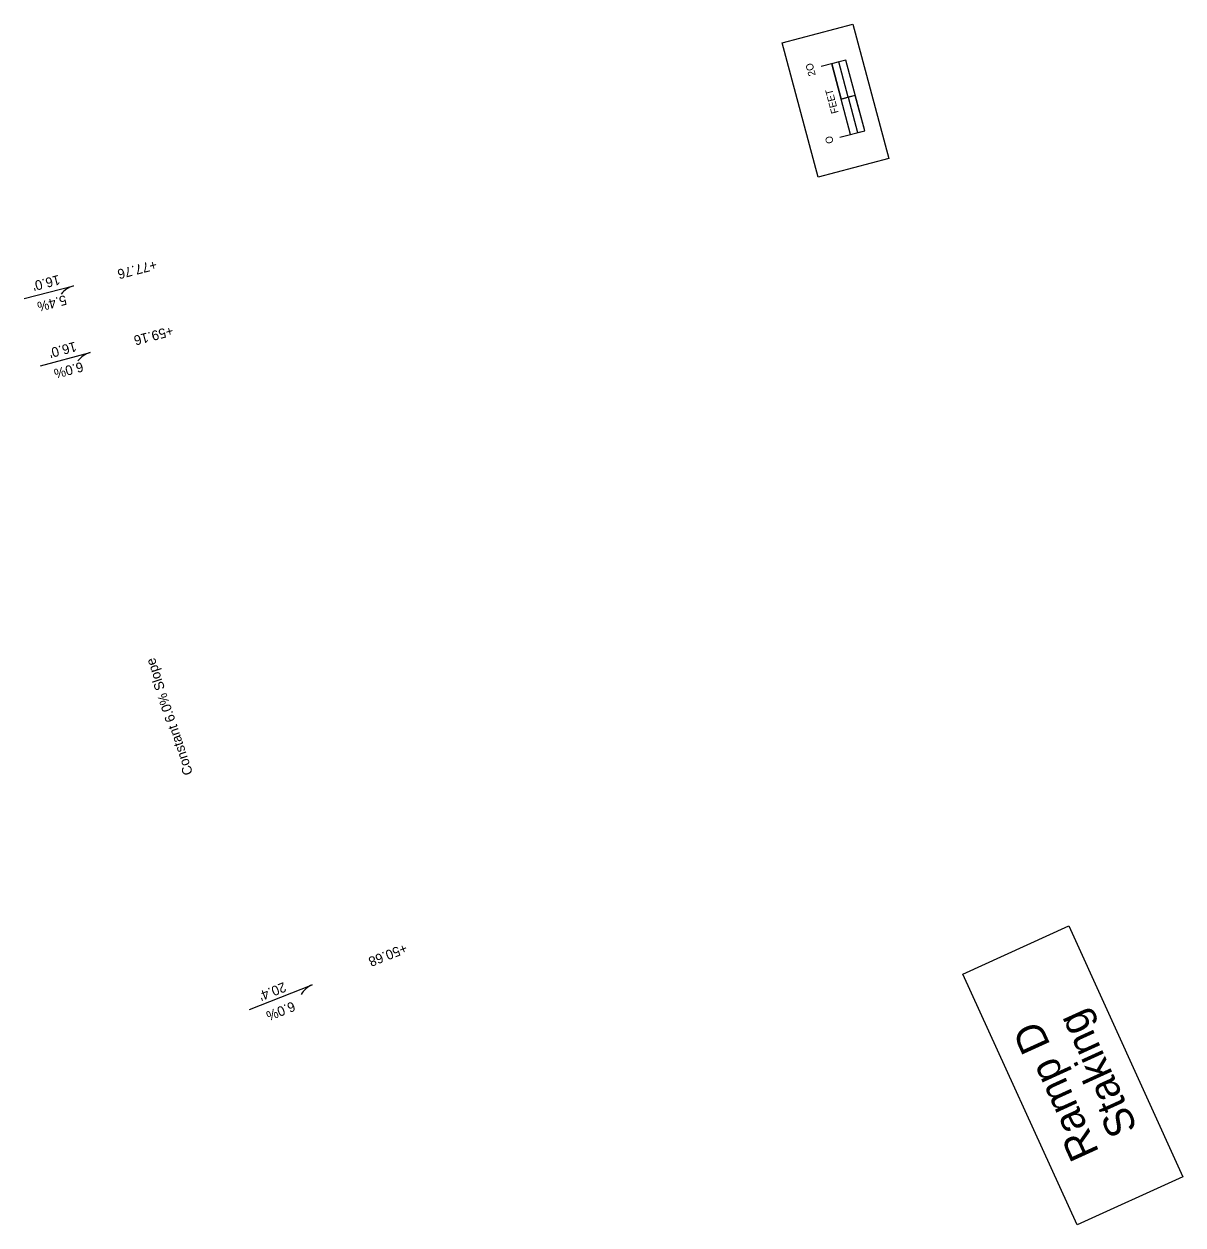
# Model space of a CAD drawing. Extents: x 20506035 to 20507470, y 7969245 to 7972296.
# Drawn here: x 20506815.4 to 20507132, y 7971126.6 to 7971454.8 of the extents above; entities that cross this region are included whole.
import ezdxf

# ---------------------------------------------------------------- set-up
doc = ezdxf.new("R2010")
doc.units = 0
doc.layers.add('_CIVIL_CONSTRUCTION', color=7, linetype='Continuous')
doc.layers.add('Joints', color=7, linetype='Continuous')

msp = doc.modelspace()

# ---------------------------------------------------------------- linework, layer by layer
at = {"layer": '_CIVIL_CONSTRUCTION'}
for p, q in [((20507042.48, 7971435.26), (20507038.62, 7971434.23)), ((20507042.48, 7971435.26), (20507038.62, 7971434.23)), ((20506815.42, 7971379.71), (20506828.94, 7971383.18)), ((20506819.96, 7971361.38), (20506833.46, 7971364.96)), ((20506877.05, 7971185.46), (20506894.16, 7971192.19))]:
    msp.add_line(p, q, dxfattribs=at)
for points in [[(20507032.3, 7971412.88), (20507022.52, 7971449.6), (20507041.84, 7971454.75), (20507051.63, 7971418.03)], [(20507032.3, 7971412.88), (20507022.52, 7971449.6), (20507041.84, 7971454.75), (20507051.63, 7971418.03)], [(20507040.54, 7971434.74), (20507037.96, 7971444.4), (20507036.04, 7971443.89), (20507038.62, 7971434.23)], [(20507045.06, 7971425.6), (20507042.48, 7971435.26), (20507040.54, 7971434.74), (20507043.11, 7971425.08)]]:
    msp.add_lwpolyline(points, close=True, dxfattribs=at)
for points in [[(20507038.29, 7971423.79), (20507045.06, 7971425.6), (20507039.91, 7971444.92), (20507033.14, 7971443.12)], [(20507041.19, 7971424.57), (20507036.04, 7971443.89)]]:
    msp.add_lwpolyline(points, dxfattribs=at)
for centre, start, end in [((20506830.47, 7971377.21), 104.3909, 142.594), ((20506835.04, 7971359.01), 104.8493, 143.0523), ((20506896.42, 7971186.46), 111.4556, 149.6587)]:
    msp.add_arc(centre, 6.16, start, end, dxfattribs=at)
at = {"layer": 'Joints'}
for points in [[(20507100.78, 7971208.3), (20507131.99, 7971139.77), (20507103.05, 7971126.58), (20507071.83, 7971195.12)], [(20507103.05, 7971126.58), (20507071.83, 7971195.12), (20507100.78, 7971208.3), (20507131.99, 7971139.77)]]:
    msp.add_lwpolyline(points, close=True, dxfattribs=at)

# ---------------------------------------------------------------- texts
at = {"layer": '_CIVIL_CONSTRUCTION'}
for s, height, rotation, p in [('2O', 2, 104.923, (20507031.69, 7971440.8)), ('FEET', 2, 104.923, (20507037.94, 7971430.55)), ('O', 2, 104.923, (20507036.61, 7971422.33)), ('+77.76', 2.664, 194.4172, (20506851.36, 7971390.32)), ("16.0'", 2.664, 194.5199, (20506824.86, 7971386.23)), ('5.4%', 2.664, 194.5199, (20506826.66, 7971380.71)), ('+59.16', 2.664, 194.8755, (20506855.81, 7971372.28)), ("16.0'", 2.664, 194.9783, (20506829.35, 7971367.98)), ('6.0%', 2.664, 194.9783, (20506831.2, 7971362.47)), ('Constant 6.0% Slope', 2.664, 108.2612, (20506861.59, 7971250)), ('+50.68', 2.664, 201.4876, (20506919.47, 7971203.59)), ("20.4'", 2.664, 201.5846, (20506886.36, 7971193)), ('6.0%', 2.664, 201.5846, (20506888.84, 7971187.74))]:
    msp.add_text(s, height=height, rotation=rotation, dxfattribs=at).set_placement(p)
at = {"layer": 'Joints'}
for s, p in [('Staking', (20507119.72, 7971152.95)), ('Ramp D', (20507109.21, 7971146.5))]:
    msp.add_text(s, height=8.16, rotation=114.4879, dxfattribs=at).set_placement(p)

doc.saveas('drawing.dxf')
